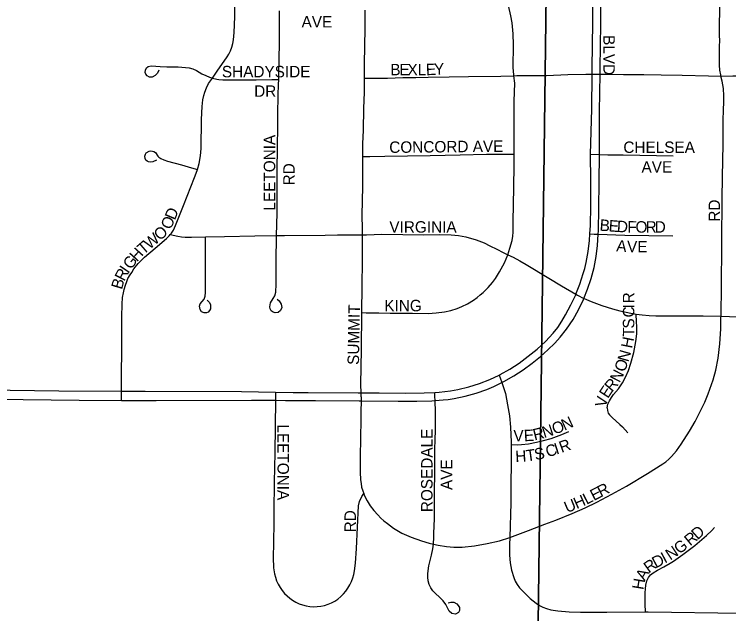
# Model space of a CAD drawing. Extents: x -97 to 34, y -21 to 22.
# Drawn here: x 6.163 to 6.753, y 18.496 to 18.991 of the extents above; entities that cross this region are included whole.
import ezdxf

# ---------------------------------------------------------------- set-up
doc = ezdxf.new("R2010")
doc.units = 0
for name, color, linetype in [('GM_X_City_Street', 7, 'Continuous'), ('GM_X_City_Street_Text', 7, 'Continuous'), ('GM_X_Section', 7, 'Continuous')]:
    doc.layers.add(name, color=color, linetype=linetype)

msp = doc.modelspace()

# ---------------------------------------------------------------- linework, layer by layer
at = {"layer": 'GM_X_City_Street'}
for points in [[(6.6468, 18.94164), (6.64685, 18.94792), (6.64705, 18.96333), (6.64738, 18.98501), (6.64766, 19.01316), (6.64784, 19.02818), (6.64805, 19.04322), (6.64861, 19.07034), (6.6488, 19.09203), (6.64888, 19.11059), (6.64897, 19.11996), (6.64967, 19.12918), (6.65064, 19.13526), (6.65141, 19.13821), (6.65245, 19.14109), (6.65378, 19.14389), (6.65546, 19.1465), (6.65745, 19.14889), (6.65947, 19.15088), (6.66566, 19.15701), (6.66722, 19.1589), (6.6685, 19.16045), (6.67101, 19.1644)], [(6.64027, 18.94164), (6.64029, 18.94684), (6.64083, 18.98398), (6.64101, 19.02738), (6.64145, 19.06456), (6.64168, 19.07384), (6.64191, 19.08313), (6.64266, 19.12035), (6.64305, 19.12953)], [(6.74664, 18.94016), (6.74645, 18.94121), (6.74566, 18.94486), (6.74551, 18.94902), (6.74548, 18.95198), (6.74553, 18.96406), (6.74555, 18.96995), (6.74548, 18.97295), (6.74542, 18.98222), (6.74559, 18.99464), (6.74568, 18.99753), (6.74608, 19.02824), (6.74665, 19.04373), (6.74658, 19.05304), (6.74676, 19.06376), (6.74686, 19.07419), (6.74716, 19.09287), (6.74703, 19.09882), (6.74702, 19.1018), (6.74702, 19.10447), (6.74698, 19.12122)], [(6.57553, 18.94038), (6.57549, 18.94105), (6.57509, 18.94724), (6.57512, 18.96583), (6.57507, 18.97513), (6.57422, 18.98417), (6.57311, 18.98986), (6.571, 18.9984), (6.56939, 19.00669), (6.56937, 19.00724)], [(6.32646, 18.93826), (6.33041, 18.94403), (6.33866, 18.95592), (6.34019, 18.95828), (6.34152, 18.96109), (6.3426, 18.964), (6.3434, 18.96699), (6.34395, 18.97005), (6.34451, 18.9762), (6.34482, 18.98233), (6.34492, 18.98924), (6.34509, 19.00062)], [(6.38188, 18.96434), (6.38188, 18.9683), (6.38188, 18.97737), (6.38204, 18.98595), (6.38204, 18.99404)], [(6.45204, 18.9385), (6.4522, 18.94975), (6.45238, 18.96531), (6.45256, 18.97881), (6.45256, 18.98987), (6.45268, 18.99463)], [(6.38128, 18.93725), (6.38139, 18.9452), (6.38155, 18.9518), (6.38172, 18.95741), (6.38188, 18.96434)], [(6.28225, 18.94502), (6.28126, 18.94254), (6.27928, 18.94056), (6.27681, 18.93908), (6.2745, 18.93908), (6.27252, 18.94023), (6.27153, 18.94155), (6.27087, 18.94303), (6.2712, 18.94485), (6.27219, 18.94682), (6.2735, 18.94798), (6.27598, 18.94865), (6.2798, 18.94831), (6.2834, 18.94799), (6.28885, 18.94782), (6.2928, 18.94783), (6.29826, 18.94775), (6.30439, 18.94731), (6.30743, 18.94682), (6.31041, 18.94607), (6.31326, 18.94469), (6.31788, 18.94205), (6.32101, 18.94057), (6.32398, 18.93925), (6.32646, 18.93826)], [(6.45204, 18.9385), (6.45496, 18.93846), (6.4609, 18.93846), (6.47113, 18.93846), (6.48383, 18.9388), (6.49457, 18.93896), (6.50478, 18.93913), (6.5221, 18.93946), (6.53794, 18.93964), (6.56466, 18.93997), (6.57553, 18.94038)], [(6.57553, 18.94038), (6.57786, 18.94047), (6.58776, 18.94047), (6.6026, 18.94064), (6.62009, 18.9413), (6.63494, 18.94164), (6.64027, 18.94164)], [(6.57566, 18.87562), (6.57574, 18.88205), (6.57568, 18.90069), (6.57584, 18.91932), (6.57622, 18.93417), (6.57553, 18.94038)], [(6.63887, 18.87551), (6.63998, 18.91273), (6.64027, 18.94164)], [(6.64027, 18.94164), (6.6468, 18.94164)], [(6.64616, 18.87539), (6.64626, 18.88637), (6.64639, 18.91088), (6.6468, 18.94164)], [(6.6468, 18.94164), (6.65159, 18.94164), (6.66611, 18.94148), (6.68294, 18.94132), (6.69729, 18.94099), (6.71445, 18.94083), (6.73622, 18.94034), (6.74664, 18.94016)], [(6.74664, 18.94016), (6.75635, 18.94018), (6.77434, 18.94025), (6.80783, 18.93954), (6.81477, 18.93944)], [(6.74669, 18.74162), (6.74685, 18.7466), (6.74712, 18.7621), (6.74737, 18.80444), (6.74742, 18.81982), (6.74759, 18.82212), (6.74766, 18.83244), (6.74765, 18.83991), (6.74786, 18.85523), (6.74799, 18.85816), (6.74798, 18.86071), (6.74809, 18.86651), (6.74816, 18.87221), (6.7483, 18.88194), (6.7483, 18.89057), (6.74849, 18.8979), (6.74849, 18.90353), (6.74868, 18.91218), (6.74886, 18.91856), (6.7489, 18.92385), (6.7486, 18.9298), (6.74773, 18.93603), (6.74664, 18.94016)], [(6.31413, 18.863), (6.3156, 18.868), (6.31665, 18.8741), (6.31715, 18.88028), (6.3174, 18.90411), (6.31805, 18.91484), (6.31871, 18.92045), (6.31937, 18.92408), (6.32019, 18.92688), (6.32151, 18.93035), (6.32333, 18.93397), (6.32646, 18.93826)], [(6.32646, 18.93826), (6.33009, 18.9376), (6.33191, 18.93727), (6.33521, 18.93711), (6.3385, 18.93695), (6.34807, 18.93695), (6.36277, 18.93707), (6.37561, 18.93719), (6.38128, 18.93725)], [(6.3795, 18.80828), (6.37993, 18.82693), (6.38009, 18.836), (6.38009, 18.84705), (6.38009, 18.86075), (6.38025, 18.88252), (6.38058, 18.8972), (6.38057, 18.90792), (6.38057, 18.91353), (6.38073, 18.91914), (6.38073, 18.92426), (6.38106, 18.93316), (6.38128, 18.93725)], [(6.45085, 18.87363), (6.4509, 18.88414), (6.45128, 18.89539), (6.45166, 18.91327), (6.45202, 18.92669), (6.45204, 18.9385)], [(6.28038, 18.87049), (6.27731, 18.86932), (6.27522, 18.86899), (6.27373, 18.86925), (6.27255, 18.86977), (6.27158, 18.87061), (6.27092, 18.87205), (6.27073, 18.87401), (6.27112, 18.8755), (6.27184, 18.87667), (6.27412, 18.87818), (6.27568, 18.87837), (6.27705, 18.87818), (6.27822, 18.87772), (6.27939, 18.87687), (6.28143, 18.87398), (6.28233, 18.87309), (6.28379, 18.87211), (6.2865, 18.87081), (6.28936, 18.86987), (6.30108, 18.86668), (6.30932, 18.86436), (6.31413, 18.863)], [(6.45085, 18.87363), (6.45666, 18.87374), (6.46905, 18.87398), (6.50634, 18.87447), (6.53111, 18.87499), (6.55293, 18.87546), (6.56824, 18.87562), (6.57566, 18.87562)], [(6.57043, 18.79248), (6.57229, 18.7978), (6.57402, 18.80411), (6.57464, 18.80794), (6.57489, 18.81116), (6.57482, 18.81995), (6.5755, 18.84797), (6.5757, 18.86654), (6.57566, 18.87562)], [(6.63831, 18.80986), (6.63875, 18.81664), (6.63912, 18.8327), (6.6392, 18.85384), (6.63887, 18.87551)], [(6.63887, 18.87551), (6.64616, 18.87539)], [(6.64516, 18.80939), (6.64536, 18.8123), (6.64583, 18.83089), (6.64595, 18.85251), (6.64616, 18.87539)], [(6.64616, 18.87539), (6.65322, 18.87514), (6.66576, 18.87489), (6.70706, 18.87429)], [(6.45036, 18.80897), (6.45036, 18.81385), (6.45035, 18.82528), (6.45067, 18.84882), (6.45074, 18.86063), (6.45085, 18.87363)], [(6.29172, 18.80914), (6.29284, 18.81041), (6.29449, 18.81288), (6.29613, 18.81652), (6.30249, 18.83319), (6.31159, 18.85627), (6.31386, 18.86206), (6.31413, 18.863)], [(6.45036, 18.80897), (6.45369, 18.80902), (6.46656, 18.80939), (6.50129, 18.80904), (6.51372, 18.80912), (6.52373, 18.80891), (6.52967, 18.8083), (6.53598, 18.80718), (6.5444, 18.80471), (6.55096, 18.80223), (6.55581, 18.79988), (6.56133, 18.79719), (6.56676, 18.79436), (6.57043, 18.79248)], [(6.62677, 18.75989), (6.62998, 18.76813), (6.6329, 18.77696), (6.63419, 18.78122), (6.63516, 18.78598), (6.63684, 18.79511), (6.63794, 18.80431), (6.63831, 18.80986)], [(6.6334, 18.75639), (6.63635, 18.76408), (6.63931, 18.7729), (6.64175, 18.78182), (6.64347, 18.7909), (6.6445, 18.8), (6.64516, 18.80939)], [(6.63831, 18.80986), (6.64194, 18.80961), (6.64516, 18.80939)], [(6.64516, 18.80939), (6.66724, 18.80869), (6.70682, 18.80797)], [(6.25146, 18.67981), (6.25146, 18.68421), (6.25146, 18.69542), (6.25163, 18.71159), (6.25178, 18.72924), (6.25178, 18.74112), (6.25194, 18.75168), (6.25227, 18.75712), (6.25293, 18.76108), (6.25359, 18.76372), (6.25458, 18.76735), (6.25573, 18.77032), (6.25672, 18.77279), (6.25853, 18.77576), (6.25992, 18.77786), (6.26167, 18.78088), (6.2653, 18.78516), (6.27041, 18.79044), (6.27928, 18.79793), (6.28857, 18.80602), (6.29082, 18.80812), (6.29172, 18.80914)], [(6.29172, 18.80914), (6.29788, 18.80774), (6.3011, 18.8072), (6.30389, 18.80699), (6.30927, 18.807), (6.3209, 18.80722)], [(6.32205, 18.75499), (6.32403, 18.75301), (6.32502, 18.7512), (6.32502, 18.74955), (6.32502, 18.7479), (6.32419, 18.74641), (6.32304, 18.74509), (6.32172, 18.74443), (6.31958, 18.74443), (6.31743, 18.74526), (6.31634, 18.74722), (6.31595, 18.74988), (6.31644, 18.75202), (6.31809, 18.75383), (6.31974, 18.75582), (6.32052, 18.75828), (6.3209, 18.76131), (6.32085, 18.7644), (6.32089, 18.77429), (6.32089, 18.78831), (6.32088, 18.79491), (6.32089, 18.79932), (6.3209, 18.80722)], [(6.3209, 18.80722), (6.33662, 18.80751), (6.36161, 18.808), (6.3795, 18.80828)], [(6.37995, 18.75567), (6.3816, 18.75434), (6.38342, 18.75171), (6.38391, 18.7489), (6.38276, 18.74627), (6.38094, 18.74461), (6.3783, 18.74444), (6.37665, 18.74511), (6.375, 18.74626), (6.37435, 18.74774), (6.37385, 18.74956), (6.37451, 18.7527), (6.37682, 18.75633), (6.37814, 18.75847), (6.37896, 18.7616), (6.37929, 18.76804), (6.37923, 18.77821), (6.37928, 18.7908), (6.37945, 18.80416), (6.3795, 18.80828)], [(6.3795, 18.80828), (6.38611, 18.80838), (6.41966, 18.80876), (6.42993, 18.80889), (6.45036, 18.80897)], [(6.44981, 18.74472), (6.44981, 18.74505), (6.45018, 18.76624), (6.45036, 18.78761), (6.45036, 18.7996), (6.45036, 18.80897)], [(6.44981, 18.74472), (6.45361, 18.7446), (6.46392, 18.74434), (6.47322, 18.74422), (6.49183, 18.74423), (6.50473, 18.74395), (6.51141, 18.74444), (6.5181, 18.74531), (6.52342, 18.7463), (6.52874, 18.74816), (6.53245, 18.74965), (6.53716, 18.752), (6.5421, 18.75485), (6.5452, 18.7572), (6.54779, 18.7593), (6.55027, 18.76141), (6.55423, 18.76537), (6.55782, 18.76945), (6.56041, 18.77292), (6.56375, 18.77837), (6.56772, 18.78591), (6.57043, 18.79248)], [(6.57043, 18.79248), (6.5749, 18.79038), (6.58037, 18.78747), (6.58574, 18.78434), (6.60442, 18.77323), (6.61484, 18.76683), (6.62677, 18.75989)], [(6.56337, 18.69304), (6.5641, 18.69339), (6.57223, 18.69792), (6.58001, 18.70301), (6.58748, 18.70856), (6.59468, 18.71445), (6.60153, 18.72075), (6.60789, 18.72754), (6.61173, 18.7324), (6.61515, 18.73755), (6.61821, 18.74291), (6.62262, 18.75107), (6.62661, 18.75946), (6.62677, 18.75989)], [(6.56566, 18.68682), (6.56728, 18.68766), (6.57537, 18.69228), (6.58321, 18.69731), (6.59069, 18.70284), (6.59745, 18.70832), (6.60364, 18.71377), (6.60929, 18.71929), (6.61367, 18.72442), (6.61899, 18.7311), (6.62445, 18.73888), (6.62904, 18.74697), (6.63301, 18.75539), (6.6334, 18.75639)], [(6.62677, 18.75989), (6.62821, 18.75905), (6.6334, 18.75639)], [(6.6334, 18.75639), (6.63374, 18.75622), (6.63944, 18.75378), (6.64818, 18.75048), (6.65709, 18.74769), (6.66311, 18.74609), (6.67222, 18.74412), (6.67656, 18.74335)], [(6.4493, 18.6784), (6.44925, 18.68533), (6.44963, 18.71431), (6.44981, 18.74472)], [(6.57226, 18.55891), (6.58759, 18.56464), (6.60112, 18.56972), (6.61032, 18.5731), (6.62366, 18.57855), (6.63455, 18.58344), (6.64394, 18.58795), (6.65652, 18.59453), (6.66855, 18.60129), (6.68601, 18.61181), (6.69858, 18.61961), (6.70111, 18.62146), (6.70351, 18.6235), (6.70576, 18.62571), (6.70992, 18.63042), (6.71381, 18.63605), (6.72075, 18.64676), (6.72544, 18.65465), (6.72901, 18.66198), (6.73333, 18.67065), (6.73596, 18.67757), (6.74009, 18.68902), (6.74239, 18.6972), (6.74422, 18.70706), (6.74576, 18.71873), (6.74664, 18.73113), (6.74661, 18.74047), (6.74669, 18.74162)], [(6.65263, 18.66597), (6.65321, 18.66897), (6.65445, 18.67178), (6.65606, 18.6744), (6.65796, 18.67691), (6.66186, 18.68167), (6.6652, 18.6865), (6.66784, 18.69143), (6.67022, 18.69693), (6.67219, 18.70279), (6.67462, 18.71179), (6.67641, 18.72088), (6.67708, 18.72701), (6.67713, 18.73309), (6.6769, 18.73704), (6.67656, 18.74335)], [(6.67656, 18.74335), (6.6815, 18.74277), (6.68733, 18.7422), (6.69285, 18.74187), (6.69525, 18.7419), (6.70102, 18.7419), (6.71017, 18.74201), (6.71944, 18.74202), (6.73189, 18.74187), (6.74669, 18.74162)], [(6.74669, 18.74162), (6.75365, 18.74151), (6.7847, 18.74118), (6.80957, 18.74096), (6.81276, 18.74098)], [(6.51024, 18.67875), (6.5139, 18.67893), (6.52313, 18.67993), (6.52922, 18.68099), (6.5382, 18.68319), (6.54706, 18.68596), (6.5557, 18.68937), (6.56337, 18.69304)], [(6.56337, 18.69304), (6.56418, 18.69083), (6.56566, 18.68682)], [(6.51047, 18.67194), (6.51711, 18.67245), (6.52136, 18.67291), (6.52631, 18.6738), (6.53544, 18.67562), (6.54443, 18.67806), (6.55323, 18.68112), (6.55895, 18.6835), (6.56566, 18.68682)], [(6.56566, 18.68682), (6.56864, 18.67783), (6.57034, 18.66855), (6.57184, 18.65932), (6.57281, 18.65), (6.5733, 18.6375), (6.5733, 18.63575)], [(5.95066, 18.68279), (5.96572, 18.68272), (5.98449, 18.68264), (6.01885, 18.68229), (6.05323, 18.6819), (6.11903, 18.68123), (6.19959, 18.68001), (6.25146, 18.67981)], [(6.25147, 18.67203), (6.25146, 18.67981)], [(6.25146, 18.67981), (6.25559, 18.67978), (6.27096, 18.67967), (6.35049, 18.67945), (6.37866, 18.67898)], [(5.95347, 18.67421), (5.95975, 18.67417), (5.98759, 18.67399), (6.03395, 18.67369), (6.08653, 18.67337), (6.17005, 18.67273), (6.21644, 18.6724), (6.25147, 18.67203)], [(6.37866, 18.67898), (6.37863, 18.67504), (6.37861, 18.67221)], [(6.37866, 18.67898), (6.39331, 18.67874), (6.40561, 18.67857), (6.44684, 18.67841), (6.4493, 18.6784)], [(6.44932, 18.67513), (6.44929, 18.67166)], [(6.4493, 18.6784), (6.4643, 18.67834), (6.48602, 18.67818), (6.50153, 18.67831), (6.51024, 18.67875)], [(6.44932, 18.67513), (6.4493, 18.6784)], [(6.51047, 18.67194), (6.51035, 18.67546), (6.51024, 18.67875)], [(6.25147, 18.67203), (6.25331, 18.67198), (6.28004, 18.67199), (6.35883, 18.6724), (6.37861, 18.67221)], [(6.37861, 18.67221), (6.37846, 18.65043), (6.37813, 18.62888), (6.3776, 18.60467), (6.3773, 18.58033), (6.37726, 18.57151), (6.37685, 18.55445), (6.37666, 18.54224), (6.37685, 18.53379), (6.37781, 18.52892), (6.37857, 18.52593), (6.37958, 18.52301), (6.38083, 18.52019), (6.38234, 18.51751), (6.38408, 18.515), (6.38604, 18.51267), (6.38814, 18.5106), (6.39036, 18.50874), (6.39276, 18.50698), (6.39536, 18.50541), (6.39811, 18.50414), (6.40095, 18.50311), (6.40389, 18.50237), (6.40689, 18.50187), (6.40995, 18.50167), (6.41301, 18.50174), (6.41608, 18.50212), (6.4191, 18.50274), (6.42206, 18.50365), (6.42491, 18.50481), (6.42762, 18.50629), (6.43016, 18.50801), (6.43251, 18.50998), (6.43466, 18.5122), (6.43664, 18.51457), (6.43845, 18.51707), (6.44005, 18.51971), (6.44141, 18.52249), (6.44251, 18.52537), (6.44334, 18.52835), (6.44396, 18.53138), (6.4448, 18.53751), (6.44558, 18.54983), (6.4471, 18.5851), (6.44803, 18.58846), (6.4499, 18.59259), (6.45155, 18.59506)], [(6.37861, 18.67221), (6.38677, 18.67217), (6.41161, 18.67201), (6.44761, 18.67168), (6.44929, 18.67166)], [(6.44929, 18.67166), (6.44922, 18.66256), (6.44917, 18.65636), (6.44848, 18.62535), (6.44852, 18.6129), (6.44884, 18.60662), (6.44932, 18.60348), (6.44972, 18.60049), (6.45066, 18.59748), (6.45155, 18.59506)], [(6.44929, 18.67166), (6.47993, 18.67138), (6.49545, 18.67136), (6.50785, 18.67171), (6.51047, 18.67194)], [(6.50906, 18.55331), (6.50938, 18.55902), (6.50955, 18.56211), (6.5099, 18.57449), (6.50992, 18.58068), (6.50995, 18.58348), (6.50994, 18.58687), (6.50996, 18.59197), (6.51001, 18.59975), (6.51013, 18.60899), (6.51034, 18.61481), (6.51038, 18.61891), (6.51038, 18.62229), (6.51038, 18.62661), (6.51037, 18.63198), (6.51056, 18.63938), (6.51075, 18.64783), (6.51079, 18.66236), (6.51047, 18.67194)], [(6.65263, 18.66597), (6.65279, 18.6639), (6.65353, 18.66167), (6.65465, 18.66006), (6.65687, 18.65795), (6.66305, 18.6522), (6.6652, 18.65015), (6.66741, 18.64788), (6.66967, 18.64536)], [(6.5733, 18.63575), (6.57832, 18.63549), (6.58172, 18.63559), (6.58765, 18.63634), (6.59421, 18.63758), (6.60015, 18.63894), (6.60634, 18.64055), (6.61522, 18.64393), (6.62107, 18.64645)], [(6.5733, 18.63575), (6.57293, 18.58742), (6.57226, 18.55891)], [(6.45155, 18.59506), (6.45197, 18.59391), (6.45423, 18.58921), (6.45686, 18.58508), (6.45986, 18.58114), (6.46325, 18.57757), (6.46569, 18.57494), (6.46813, 18.57269), (6.47114, 18.57044), (6.47621, 18.56668), (6.48297, 18.56255), (6.49067, 18.55898), (6.49913, 18.55617), (6.50552, 18.5541), (6.50906, 18.55331)], [(6.68434, 18.49733), (6.68411, 18.50382), (6.684, 18.50696), (6.68402, 18.51324), (6.68418, 18.51638), (6.68456, 18.5195), (6.68545, 18.52304), (6.68681, 18.52577), (6.68854, 18.528), (6.69052, 18.52973), (6.69411, 18.53171), (6.69937, 18.53462), (6.70471, 18.53762), (6.70733, 18.53926), (6.71505, 18.54469), (6.72504, 18.55228), (6.73455, 18.56046), (6.73911, 18.56475), (6.74131, 18.56698)], [(6.50906, 18.55331), (6.51303, 18.55242), (6.51979, 18.55129), (6.52599, 18.55091), (6.53294, 18.55092), (6.54289, 18.55186), (6.5536, 18.55374), (6.56375, 18.55618), (6.57226, 18.55891)], [(6.57226, 18.55891), (6.57184, 18.55302), (6.57179, 18.55045), (6.57192, 18.54418), (6.57251, 18.53793), (6.57364, 18.53172), (6.57546, 18.52568), (6.57669, 18.52273), (6.57829, 18.51992), (6.58022, 18.51737), (6.58449, 18.51273), (6.58905, 18.50845), (6.59397, 18.50448), (6.59667, 18.50278), (6.59955, 18.50136), (6.60258, 18.50029), (6.60621, 18.49916), (6.61191, 18.49817), (6.62115, 18.49739), (6.63053, 18.49719), (6.65225, 18.49708), (6.68434, 18.49733)], [(6.52131, 18.50489), (6.52356, 18.50546), (6.526, 18.50527), (6.52844, 18.50414), (6.5295, 18.50259), (6.53051, 18.50095), (6.53073, 18.49977), (6.53069, 18.49851), (6.52985, 18.49691), (6.52723, 18.4954), (6.52428, 18.4959), (6.52205, 18.49797), (6.5206, 18.50075), (6.51934, 18.50359), (6.51717, 18.50658), (6.51398, 18.5094), (6.51086, 18.5125), (6.50871, 18.51472), (6.5069, 18.51723), (6.50555, 18.52002), (6.50471, 18.52299), (6.50437, 18.52606), (6.50444, 18.52916), (6.50527, 18.5353), (6.50758, 18.54434), (6.50871, 18.54941), (6.50906, 18.55331)], [(6.68434, 18.49733), (6.68635, 18.49734), (6.76339, 18.49623)]]:
    msp.add_lwpolyline(points, dxfattribs=at)
at = {"layer": 'GM_X_Section'}
for points in [[(5.59615, 19.47364), (6.60805, 19.46219), (6.59547, 18.46625), (5.59082, 18.47236)], [(6.60805, 19.46219), (7.61097, 19.41205), (7.59861, 18.45475), (6.59547, 18.46625)]]:
    msp.add_lwpolyline(points, close=True, dxfattribs=at)

# ---------------------------------------------------------------- texts
at = {"layer": 'GM_X_City_Street_Text'}
for s, height, rotation, p in [('AVE', 0.00947, 0.00001, (6.40016, 18.98027)), ('BLVD', 0.00947, 270, (6.64944, 18.97395)), ('Y', 0.00947, 3.12784, (6.50987, 18.941)), ('SHADYSIDE', 0.00947, 0.00001, (6.33432, 18.93906)), ('B', 0.00947, 0.02429, (6.47349, 18.94073)), ('E', 0.00947, 0.02732, (6.48099, 18.94073)), ('X', 0.00947, 0.02186, (6.48766, 18.94073)), ('L', 0.00947, 0.18486, (6.49602, 18.94073)), ('E', 0.00947, 1.92423, (6.50299, 18.94076)), ('DR', 0.00947, 0.00001, (6.36099, 18.92295)), ('LEETONIA', 0.00947, 90, (6.37838, 18.82895)), ('CONCORD AVE', 0.0094697, 0.5781, (6.47264, 18.87656)), ('CHELSEA', 0.00947, 0.00001, (6.66599, 18.87656)), ('AVE', 0.00947, 0.00001, (6.68099, 18.86027)), ('RD', 0.00947, 90, (6.39449, 18.84978)), ('RD', 0.00947, 90, (6.74588, 18.81978)), ('D', 0.00947, 67.47679, (6.29547, 18.82055)), ('O', 0.00947, 65.58703, (6.29188, 18.81265)), ('B', 0.00947, 355.64971, (6.64613, 18.81239)), ('E', 0.00947, 355.64632, (6.65361, 18.81182)), ('O', 0.00947, 42.18079, (6.28324, 18.80366)), ('VIRGINIA', 0.00947, 0.00001, (6.47266, 18.81073)), ('D', 0.00947, 356.60395, (6.66043, 18.81131)), ('F', 0.00947, 359.46758, (6.66927, 18.81079)), ('O', 0.00947, 359.97035, (6.67602, 18.81073)), ('R', 0.00947, 359.99406, (6.68436, 18.81073)), ('D', 0.00947, 359.99285, (6.69186, 18.81073)), ('W', 0.00947, 39.55797, (6.27453, 18.79645)), ('T', 0.00947, 40.82354, (6.26953, 18.79213)), ('A', 0.00947, 354.70266, (6.6599, 18.7954)), ('V', 0.00947, 359.02441, (6.66897, 18.79459)), ('E', 0.00947, 359.94573, (6.67747, 18.79444)), ('H', 0.00947, 47.86008, (6.26415, 18.78617)), ('G', 0.00947, 52.17292, (6.25916, 18.77973)), ('R', 0.00947, 62.67466, (6.25364, 18.77)), ('I', 0.00947, 56.00691, (6.25693, 18.77641)), ('B', 0.00947, 73.55427, (6.25169, 18.76324)), ('R', 0.00947, 90, (6.67504, 18.75232)), ('SUMMIT', 0.00947, 88.99759, (6.44754, 18.7014)), ('KING', 0.00947, 0.00001, (6.46849, 18.74573)), ('I', 0.00947, 90, (6.67504, 18.74815)), ('C', 0.00947, 89.99405, (6.67504, 18.74065)), ('S', 0.00947, 89.99561, (6.67504, 18.73148)), ('T', 0.00947, 89.6942, (6.67501, 18.72476)), ('H', 0.00947, 78.74825, (6.67318, 18.71463)), ('N', 0.00947, 74.12399, (6.67003, 18.70339)), ('O', 0.00947, 71.18708, (6.66719, 18.695)), ('N', 0.00947, 62.58873, (6.66274, 18.68618)), ('R', 0.00947, 50.02031, (6.65667, 18.67855)), ('E', 0.00947, 57.10554, (6.65323, 18.6732)), ('V', 0.00947, 76.65811, (6.65164, 18.66587)), ('N', 0.00947, 24.51056, (6.61736, 18.64697)), ('LEETONIA', 0.00947, 270, (6.38027, 18.65228)), ('N', 0.00947, 17.66515, (6.60052, 18.6409)), ('O', 0.00947, 21.76546, (6.60916, 18.64368)), ('ROSEDALE', 0.00947, 90, (6.50837, 18.57978)), ('V', 0.00947, 0.3279, (6.57517, 18.63823)), ('E', 0.00947, 2.89159, (6.58397, 18.63829)), ('R', 0.00947, 13.91559, (6.59259, 18.63892)), ('R', 0.00947, 19.90963, (6.61491, 18.62866)), ('S', 0.00947, 11.52039, (6.59341, 18.62267)), ('C', 0.00947, 17.55885, (6.6034, 18.62498)), ('I', 0.00947, 17.89163, (6.6106, 18.62726)), ('H', 0.00947, 2.93008, (6.57695, 18.62111)), ('T', 0.00947, 8.08831, (6.5862, 18.62162)), ('AVE', 0.00947, 90, (6.52467, 18.59811)), ('R', 0.00947, 27.51536, (6.64748, 18.59195)), ('E', 0.00947, 27.48028, (6.64156, 18.58887)), ('U', 0.00947, 22.47525, (6.61948, 18.57893)), ('H', 0.00947, 23.76493, (6.62739, 18.58221)), ('L', 0.00947, 26.91752, (6.63552, 18.5858)), ('RD', 0.00947, 90, (6.44505, 18.56311)), ('D', 0.00947, 41.55963, (6.72722, 18.55649)), ('R', 0.00947, 39.41434, (6.72114, 18.55148)), ('G', 0.00947, 37.21859, (6.7122, 18.54468)), ('N', 0.00947, 33.87688, (6.70479, 18.53968)), ('D', 0.00947, 28.45173, (6.69287, 18.53322)), ('I', 0.00947, 27.87455, (6.70018, 18.53718)), ('R', 0.00947, 35.46146, (6.68702, 18.52903)), ('A', 0.00947, 60.24698, (6.68361, 18.52259)), ('H', 0.00947, 80.38319, (6.68251, 18.5152))]:
    msp.add_text(s, height=height, rotation=rotation, dxfattribs=at).set_placement(p)

doc.saveas('drawing.dxf')
